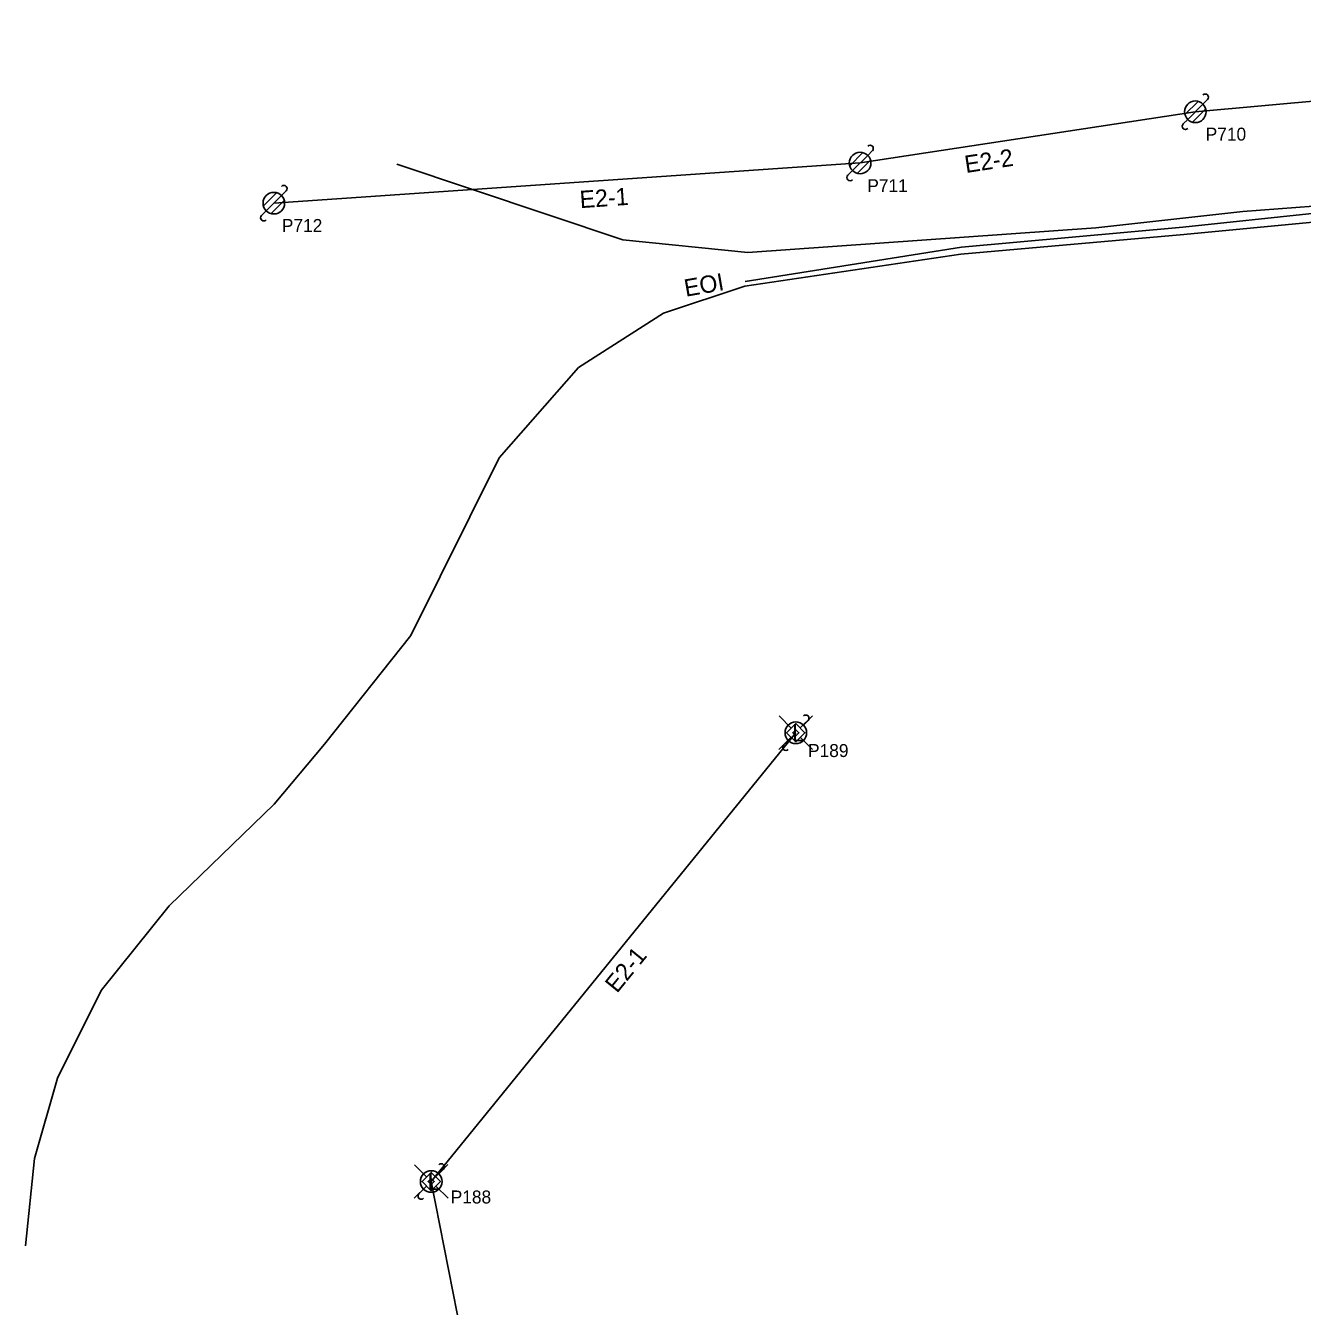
# Model space of a CAD drawing. Extents: x 1614474 to 1865144, y 1098877 to 1212550.
# Drawn here: x 1771587.2 to 1771882.6, y 1180445.7 to 1180742.2 of the extents above; entities that cross this region are included whole.
import ezdxf

# ---------------------------------------------------------------- set-up
doc = ezdxf.new("R2010")
doc.units = 0
for name, color, linetype in [('RD_EX_SU_Ovhd', 7, 'Continuous'), ('RD_EX_SU_Pole', 7, 'Continuous'), ('RD_EX_SU_Telecom', 7, 'Continuous'), ('RD_EX_SU_TX_Pole', 7, 'Continuous'), ('RD_EX_SU_TX_Telecom', 7, 'Continuous')]:
    doc.layers.add(name, color=color, linetype=linetype)

# ---------------------------------------------------------------- blocks, each defined once
blk = doc.blocks.new('SUE_PGP')
at = {"layer": 'RD_EX_SU_Pole'}
for p, q in [((-1.06, 1.06), (-3.89, 3.89)), ((1.02, 1.12), (3.86, 3.96)), ((-1.11, -1.04), (-3.94, -3.87)), ((1.06, -1.06), (3.89, -3.89))]:
    blk.add_line(p, q, dxfattribs=at)
for points in [[(0, -2.12), (2.12, 0), (0, 2.12), (-2.12, 0)], [(0, -0.71), (0.71, 0), (0, 0.71), (-0.71, 0)]]:
    blk.add_lwpolyline(points, close=True, dxfattribs=at)
blk = doc.blocks.new('SUE_PP')
at = {"layer": 'RD_EX_SU_Pole'}
for p, q in [((-2.41, -0.65), (0.65, 2.41)), ((-1.77, -1.77), (1.77, 1.77)), ((-0.65, -2.41), (2.41, 0.65)), ((1.77, 1.77), (2.83, 2.83)), ((-2.83, -2.83), (-1.77, -1.77))]:
    blk.add_line(p, q, dxfattribs=at)
blk.add_circle((0, 0), 2.5, dxfattribs=at)
for centre, start, end in [((2.3, 3.36), 315, 135), ((-2.3, -3.36), 135, 315)]:
    blk.add_arc(centre, 0.75, start, end, dxfattribs=at)

msp = doc.modelspace()

# ---------------------------------------------------------------- linework, layer by layer
at = {"layer": 'RD_EX_SU_Ovhd'}
for p, q in [((1771857.86, 1180722.29), (1772081.03, 1180742.23)), ((1771780.28, 1180710.43), (1771857.86, 1180722.29)), ((1771644.6, 1180701.13), (1771780.28, 1180710.43)), ((1771681.02, 1180474.64), (1771765.4, 1180578.52)), ((1771681.02, 1180474.64), (1771704.86, 1180353.95))]:
    msp.add_line(p, q, dxfattribs=at)
at = {"layer": 'RD_EX_SU_Pole'}
for p, q in [((1771767.17, 1180580.29), (1771768.23, 1180581.35)), ((1771762.57, 1180575.69), (1771763.63, 1180576.75)), ((1771682.79, 1180476.41), (1771683.85, 1180477.47)), ((1771678.19, 1180471.81), (1771679.25, 1180472.88))]:
    msp.add_line(p, q, dxfattribs=at)
for centre in [(1771765.4, 1180578.52), (1771681.02, 1180474.64)]:
    msp.add_circle(centre, 2.5, dxfattribs=at)
for centre, start, end in [((1771767.7, 1180581.88), 315, 135), ((1771763.1, 1180575.16), 135, 315), ((1771683.32, 1180478), 315, 135), ((1771678.72, 1180471.28), 135, 315)]:
    msp.add_arc(centre, 0.75, start, end, dxfattribs=at)
at = {"layer": 'RD_EX_SU_Telecom'}
for points in [[(1771587.15, 1180459.73), (1771589.21, 1180479.94), (1771594.54, 1180498.57), (1771604.64, 1180518.89), (1771620.34, 1180538.47), (1771644.7, 1180562.03), (1771656.29, 1180575.92), (1771676.28, 1180601.07), (1771696.75, 1180642.18), (1771715.12, 1180663.08), (1771734.81, 1180675.7), (1771753.58, 1180681.9), (1771803.62, 1180689.32), (1771855.23, 1180693.88), (1771885.92, 1180696.78), (1771929.22, 1180700.82), (1771957.5, 1180703.88), (1771977.31, 1180708.74), (1771991.43, 1180713.91), (1772007.96, 1180718.9), (1772016.21, 1180721.06), (1772018.22, 1180720.58)], [(1771673.08, 1180710.15), (1771725.33, 1180692.64), (1771754.29, 1180689.69), (1771834.8, 1180695.43), (1771868.85, 1180699.19), (1771913.8, 1180702.63), (1771941.97, 1180705.7), (1771967.65, 1180710.79), (1772000.6, 1180714.01), (1772008.52, 1180715.93), (1772018.24, 1180720.18)], [(1771753.67, 1180682.97), (1771803.71, 1180690.91), (1771855, 1180695.57), (1771885.61, 1180698.79), (1771929.06, 1180702.84), (1771957.15, 1180705.08), (1771977.25, 1180707.15), (1771991.28, 1180708.86), (1772007.5, 1180712.7), (1772015.5, 1180717.03), (1772018.36, 1180719.84)]]:
    msp.add_lwpolyline(points, dxfattribs=at)

# ---------------------------------------------------------------- block references
at = {"layer": 'RD_EX_SU_Pole'}
for name, p in [('SUE_PP', (1771857.86, 1180722.29)), ('SUE_PP', (1771780.28, 1180710.43)), ('SUE_PP', (1771644.6, 1180701.13)), ('SUE_PGP', (1771765.4, 1180578.52)), ('SUE_PGP', (1771681.02, 1180474.64))]:
    msp.add_blockref(name, p, dxfattribs=at)

# ---------------------------------------------------------------- texts
at = {"layer": 'RD_EX_SU_Ovhd'}
for s, rotation, p in [('E2-2', 8.6973, (1771804.78, 1180708.1)), ('E2-1', 3.9187, (1771715.52, 1180699.97)), ('E2-1', 50.9134, (1771724.02, 1180518.07))]:
    msp.add_text(s, height=4, rotation=rotation, dxfattribs=at).set_placement(p)
at = {"layer": 'RD_EX_SU_Pole'}
for p in [(1771764.54, 1180576.52), (1771680.16, 1180472.64)]:
    msp.add_text('L', height=4, dxfattribs=at).set_placement(p)
at = {"layer": 'RD_EX_SU_TX_Pole'}
for s, p in [('P710', (1771860.25, 1180715.61)), ('P711', (1771781.94, 1180703.68)), ('P712', (1771646.45, 1180694.46)), ('P189', (1771768.23, 1180572.91)), ('P188', (1771685.53, 1180469.56))]:
    msp.add_text(s, height=3, dxfattribs=at).set_placement(p)
at = {"layer": 'RD_EX_SU_TX_Telecom'}
msp.add_text('EOI', height=4, rotation=9.9854, dxfattribs=at).set_placement((1771739.94, 1180679.45))

doc.saveas('drawing.dxf')
